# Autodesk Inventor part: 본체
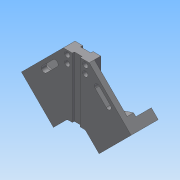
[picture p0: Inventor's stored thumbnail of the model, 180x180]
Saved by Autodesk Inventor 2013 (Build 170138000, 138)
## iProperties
Created: 2019-04
Part Number: 본체
Material: 일반
Document SubType Name: Modeling
Designer: Administrator
Density: 1 g/cm^3
Author: Administrator
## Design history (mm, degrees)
sketch "스케치3"
  geometry: L1 (0, 0)-(0, -20); L2 (0, -169.706)-(35.355, -134.35); L3 (84.853, -84.853)-(20, -20); L4 (35.355, -134.35)-(14.005, -113); L5 (14.005, -113)-(0, -113); L6 (20, -20)-(0, -20); L7 (0, -113)-(0, -169.706); L8 (35.355, -134.35)-(84.853, -84.853); L9 (0, -20)-(0, -113); L10 (20, -20)-(0, 0)
  constraints: 20 end point, 10 perpendicular, 3 vertical, 2 parallel
  dimensions: "d11" = 45 deg angle of L1 L3; "d12" = 120 distance of L3.start L1.start; "d13" = 50 distance of L2.end L2.start; "d15" = 20 distance from line of L6 L1.start; "d16" = 93 distance between parallel lines of L5 L6
extrude "돌출1" new body sketch "스케치3" distance "d17" = 18; taper "d18" = 0 deg
sketch "스케치4"
  geometry: L1 (-84.853, 84.853)-(-35.355, 134.35) reference; L2 (-35.355, 134.35)-(-14.005, 113) reference; L3 (-14.005, 113)-(0, 113) reference; L4 (0, 113)-(0, 20) reference; L5 (0, 20)-(-20, 20) reference; L6 (-20, 20)-(-84.853, 84.853) reference; L7 (-84.853, 84.853)-(-35.355, 134.35); L8 (-35.355, 134.35)-(-24.749, 123.744); L9 (-24.749, 123.744)-(-74.246, 74.246); L10 (-74.246, 74.246)-(-84.853, 84.853); 1 further point
  constraints: 8 end point, 2 parallel, 2 perpendicular
  dimensions: "d19" = 15 distance between parallel lines of L9 L7
extrude "돌출2" join sketch "스케치4" distance "d21" = 24; taper "d22" = 0 deg
sketch "스케치5"
  geometry: L1 (-84.853, 84.853)-(-35.355, 134.35) reference; L2 (-35.355, 134.35)-(-24.749, 123.744) reference; L3 (-24.749, 123.744)-(-74.246, 74.246) reference; L4 (-20, 20)-(-74.246, 74.246) reference; L5 (0, 20)-(-20, 20) reference; L6 (0, 113)-(0, 20) reference; L7 (-14.005, 113)-(0, 113) reference; L8 (-24.749, 123.744)-(-14.005, 113) reference; L9 (-74.246, 74.246)-(-84.853, 84.853) reference; L10 (-70.711, 70.711)-(-49.497, 77.782); L11 (-49.497, 77.782)-(-20, 48.284); L12 (-20, 48.284)-(-20, 20); L13 (-70.711, 70.711)-(-20, 20); 1 further point
  constraints: 8 end point, 2 parallel, 1 point on line
  dimensions: "d23" = 20 distance from line of L10.start L1; "d24" = 20 distance between parallel lines of L11 L4; "d25" = 90 deg angle of L5 L12; "d26" = 30 distance from line of L10.end L1
extrude "돌출3" cut sketch "스케치5" distance "d27" = 10; taper "d28" = 0 deg
sketch "스케치6"
  geometry: L1 (-35.355, -134.35)-(-84.853, -84.853) reference; L2 (-84.853, -84.853)-(-20, -20) reference; L3 (-20, -20)-(0, -20) reference; L4 (0, -20)-(0, -113) reference; L5 (0, -113)-(-14.005, -113) reference; L6 (-14.005, -113)-(-35.355, -134.35) reference; 3 further points
  constraints: 1 vertical alignment
  dimensions: "d29" = 6 distance from line of L3 point (-14, -26); "d30" = 12 distance of point (-14, -38) point (-14, -26); "d31" = 14 distance from line of L4 point (-14, -26)
hole "구멍1" sketch "스케치6" at (-14, -26), (-14, -38) diameter "d32" = 4.5; stored, may be unused: countersink angle "d36" = 90 deg, drill point angle "d38" = 118 deg; dims "d33" = 6, "d34" = 8, "d35" = 10, "d37" = 8
sketch "스케치7"
  geometry: L1 (-84.853, 84.853)-(-35.355, 134.35) reference; L2 (-35.355, 134.35)-(-14.005, 113) reference; L3 (-14.005, 113)-(0, 113) reference; L4 (0, 113)-(0, 20) reference; L5 (0, 20)-(-20, 20) reference; L6 (-20, 20)-(-70.711, 70.711) reference; L7 (-70.711, 70.711)-(-84.853, 84.853) reference; L8 (-20, 20)-(-20, 48.284) reference; L9 (-20, 48.284)-(-49.497, 77.782) reference; L10 (-49.497, 77.782)-(-70.711, 70.711) reference; L11 (-52.679, 60.458)-(-35.709, 43.487); L12 (-29.345, 49.851)-(-46.315, 66.822); C1 r 4 at (-14, 26) reference; C2 r 4 at (-14, 38) reference; A1 r 4.5 centre (-32.527, 46.669) between (-35.709, 43.487) and (-29.345, 49.851); A2 r 4.5 centre (-49.497, 63.64) between (-46.315, 66.822) and (-52.679, 60.458); 1 further point
  constraints: 4 end point, 4 point on circle, 3 tangent, 2 centre point, 2 parallel
  dimensions: "d39" = 40 distance from line of A2.centre L1; "d41" = 9 distance between parallel lines of L12 L11; "d42" = 10 distance from line of A2.centre L6; "d43" = 10 distance from line of L6 A1.centre; "d44" = 24 distance of L11.start L11.end
extrude "돌출4" cut sketch "스케치7" distance "d45" = 10; taper "d46" = 0 deg
sketch "스케치8"
  geometry: L1 (0, 20)-(0, 113) reference; L2 (0, 113)-(-8, 113); L3 (-8, 113)-(-8, 20); L4 (-8, 20)-(0, 20); L5 (0, 20)-(0, 113); 1 further point
  constraints: 8 end point, 2 parallel, 1 horizontal, 1 perpendicular, 1 point on line
  dimensions: "d47" = 8 distance between parallel lines of L5 L3
extrude "돌출5" cut sketch "스케치8" distance "d49" = 3.5; taper "d50" = 0 deg
sketch "스케치9"
  geometry: L1 (0, -20)-(0, -113) reference; L2 (0, -20)-(-6, -20); L3 (-6, -20)-(-6, -113); L4 (-6, -113)-(0, -113); L5 (0, -113)-(0, -20); 1 further point
  constraints: 8 end point, 2 parallel, 1 horizontal, 1 perpendicular, 1 point on line
  dimensions: "d51" = 6 distance of L1.start L2.end
extrude "돌출6" cut sketch "스케치9" distance "d52" = 3; taper "d53" = 0 deg
fillet "모깎기1" dims "d54" = 5
sketch "스케치10"
  geometry: L1 (-35.355, 134.35)-(-84.853, 84.853) reference; L2 (-24.749, 123.744)-(-35.355, 134.35) reference; 2 further points
  constraints: 1 other
  dimensions: "d56" = 35 distance from line of L2 point (-54.801, 104.298); "d57" = 7.5 distance from line of L1 point (-54.801, 104.298)
feature "엠보싱1" sketch "스케치10" dims "d11" = 45 deg, "d12" = 120, "d13" = 50, "d15" = 20, "d16" = 93, "d58" = 0.5, "d59" = 0
node "솔리드1"
mirror "대칭1"
node "절단 모서리 투영1"
node "절단 모서리 투영2"
node "절단 모서리 투영3"
node "절단 모서리 투영4"
